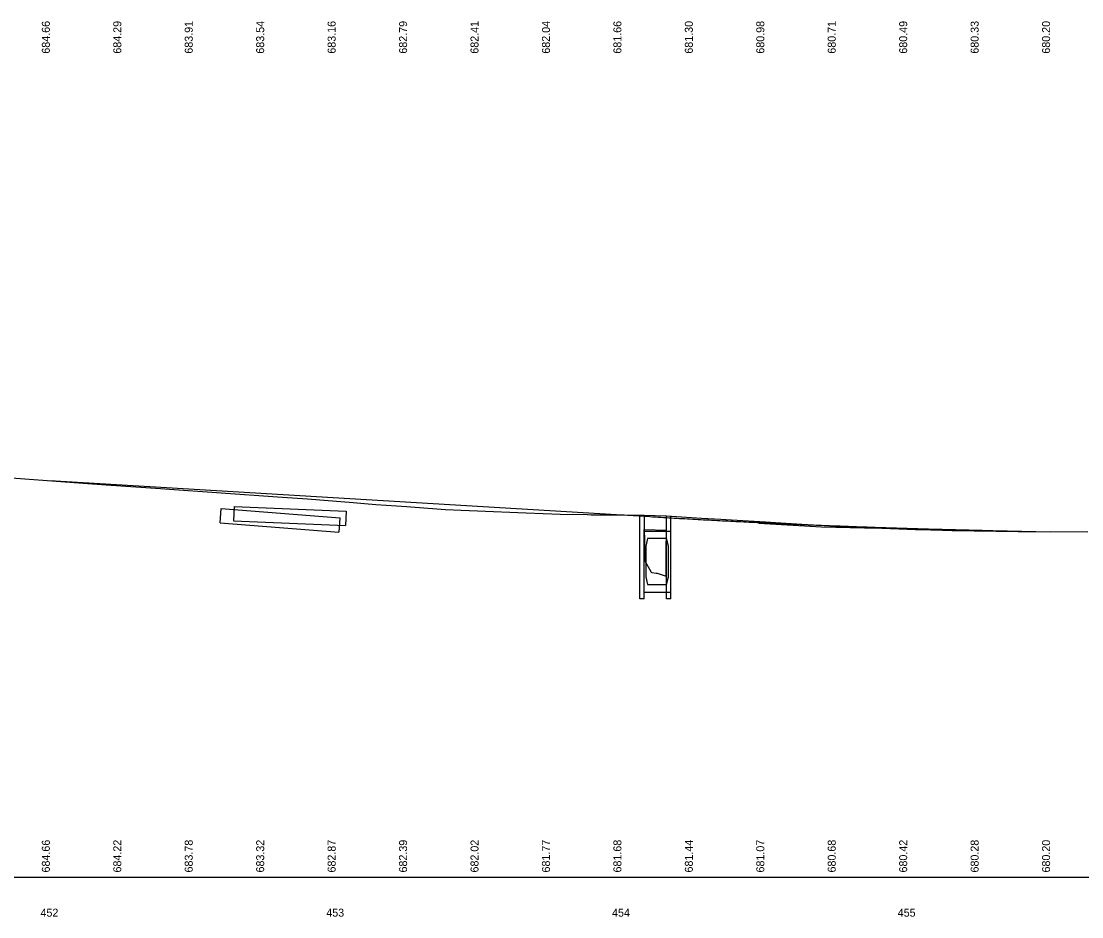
# Model space of a CAD drawing. Extents: x 157201 to 163282, y 424960 to 427200.
# Drawn here: x 161796.3 to 162167.4, y 425949.5 to 426262.7 of the extents above; entities that cross this region are included whole.
import ezdxf

# ---------------------------------------------------------------- set-up
doc = ezdxf.new("R2010")
doc.units = 0
for name, color, linetype in [('DR_X_Elev_Flow', 7, 'Continuous'), ('RD_X_Concrete_Pad', 7, 'Continuous'), ('RD_X_Fence', 7, 'Continuous'), ('RD_X_GR_Rt', 7, 'Continuous'), ('SV_X_Shot_Marker', 7, 'Continuous'), ('UT_X_Sanitary_Cells', 7, 'Continuous'), ('UT_X_Water_Cells', 7, 'Continuous')]:
    doc.layers.add(name, color=color, linetype=linetype)

msp = doc.modelspace()

# ---------------------------------------------------------------- linework, layer by layer
at = {"layer": 'DR_X_Elev_Flow'}
for p, q in [((161865.84, 426087.28), (161866.23, 426092.26)), ((161866.23, 426092.26), (161907.78, 426088.98)), ((161907.78, 426088.98), (161907.39, 426084)), ((162012.79, 426060.67), (162012.79, 426089.98)), ((162014.28, 426089.96), (162022.07, 426089.69)), ((162023.55, 426060.67), (162023.55, 426089.59)), ((161865.84, 426087.28), (161907.39, 426084)), ((162014.29, 426060.67), (162014.29, 426084.96)), ((162014.29, 426084.96), (162022.05, 426084.69)), ((162022.05, 426060.67), (162022.05, 426084.69)), ((162014.29, 426060.67), (162012.79, 426060.67)), ((162023.55, 426060.67), (162022.05, 426060.67))]:
    msp.add_line(p, q, dxfattribs=at)
at = {"layer": 'RD_X_Concrete_Pad'}
for p, q in [((161806.29, 426102.02), (162016.29, 426089.42)), ((162136.29, 426084.57), (162156.29, 426084.15))]:
    msp.add_line(p, q, dxfattribs=at)
msp.add_open_spline([(162016.29, 426089.42), (162076.29, 426085.82), (162136.29, 426084.57)], degree=2, dxfattribs=at)
at = {"layer": 'SV_X_Shot_Marker'}
for p, q in [((162054.42, 426087.13), (162076.29, 426085.82)), ((162076.29, 426085.82), (162096.33, 426085.4)), ((161406.29, 425963.36), (162615.86, 425963.36))]:
    msp.add_line(p, q, dxfattribs=at)
at = {"layer": 'UT_X_Sanitary_Cells'}
for p, q in [((161870.77, 426092.92), (161870.57, 426087.92)), ((161870.77, 426092.92), (161909.96, 426091.32)), ((161909.96, 426091.32), (161909.76, 426086.32)), ((161870.57, 426087.92), (161909.76, 426086.32)), ((162014.12, 426084.39), (162023.46, 426084.39)), ((162014.12, 426084.39), (162014.12, 426063.05)), ((162023.46, 426084.39), (162023.46, 426063.05)), ((162015.46, 426081.72), (162014.79, 426079.05)), ((162022.12, 426081.72), (162015.46, 426081.72)), ((162022.79, 426079.05), (162022.12, 426081.72)), ((162014.79, 426079.05), (162014.79, 426068.39)), ((162022.79, 426068.39), (162022.79, 426079.05)), ((162014.79, 426068.39), (162015.46, 426065.72)), ((162015.46, 426065.72), (162022.12, 426065.72)), ((162022.12, 426065.72), (162022.79, 426068.39)), ((162014.12, 426063.05), (162023.46, 426063.05))]:
    msp.add_line(p, q, dxfattribs=at)
at = {"layer": 'UT_X_Water_Cells'}
msp.add_lwpolyline([(161774.19, 426104.4), (161797.53, 426102.67), (161821.14, 426100.92), (161821.33, 426100.91), (161825.96, 426100.59), (161844.98, 426099.27), (161846.47, 426099.18), (161885.94, 426096.3), (161896.4, 426095.68), (161912.45, 426094.32), (161920.34, 426093.7), (161927.56, 426093.18), (161931.09, 426092.93), (161944.71, 426091.89), (161950.27, 426091.67), (161958.68, 426091.35), (161970.03, 426090.91), (161972.98, 426090.79), (161984.81, 426090.3), (161994.37, 426090.12), (161995.69, 426090.11), (162007.23, 426090.09), (162014.28, 426089.96), (162014.43, 426076.08), (162014.44, 426074.11), (162014.51, 426073.99), (162016.67, 426070.04), (162016.9, 426069.94), (162018.4, 426069.67), (162018.53, 426069.64), (162018.75, 426069.66), (162021.57, 426068.67), (162021.98, 426068.62), (162022, 426072.27), (162022.07, 426089.69), (162034.26, 426088.92), (162041.11, 426088.51), (162042.88, 426088.4), (162056.66, 426087.61), (162063.81, 426087.15), (162069.39, 426086.8), (162081.19, 426086.08), (162086.52, 426085.88), (162090.2, 426085.75), (162094.53, 426085.45), (162109.23, 426084.93), (162114.51, 426084.75), (162118.7, 426084.64), (162122.03, 426084.62), (162145.11, 426084.23), (162169.53, 426084.06)], dxfattribs=at)

# ---------------------------------------------------------------- texts
at = {"layer": 'RD_X_Fence'}
for s, p in [('684.66', (161806.29, 425964.97)), ('684.22', (161831.29, 425964.97)), ('683.78', (161856.29, 425964.97)), ('683.32', (161881.29, 425964.97)), ('682.87', (161906.29, 425964.97)), ('682.39', (161931.29, 425964.97)), ('682.02', (161956.29, 425964.97)), ('681.77', (161981.29, 425964.97)), ('681.68', (162006.29, 425964.97)), ('681.44', (162031.29, 425964.97)), ('681.07', (162056.29, 425964.97)), ('680.68', (162081.29, 425964.97)), ('680.42', (162106.29, 425964.97)), ('680.28', (162131.29, 425964.97)), ('680.20', (162156.29, 425964.97))]:
    msp.add_text(s, height=2.8, rotation=90, dxfattribs=at).set_placement(p)
at = {"layer": 'RD_X_GR_Rt'}
for s, p in [('684.66', (161806.29, 426251.33)), ('684.29', (161831.29, 426251.33)), ('683.91', (161856.29, 426251.33)), ('683.54', (161881.29, 426251.33)), ('683.16', (161906.29, 426251.33)), ('682.79', (161931.29, 426251.33)), ('682.41', (161956.29, 426251.33)), ('682.04', (161981.29, 426251.33)), ('681.66', (162006.29, 426251.33)), ('681.30', (162031.29, 426251.33)), ('680.98', (162056.29, 426251.33)), ('680.71', (162081.29, 426251.33)), ('680.49', (162106.29, 426251.33)), ('680.33', (162131.29, 426251.33)), ('680.20', (162156.29, 426251.33))]:
    msp.add_text(s, height=2.8, rotation=90, dxfattribs=at).set_placement(p)
for s, p in [('452', (161803.01, 425949.52)), ('453', (161903.02, 425949.52)), ('454', (162003.02, 425949.52)), ('455', (162102.99, 425949.52))]:
    msp.add_text(s, height=2.8, dxfattribs=at).set_placement(p)

doc.saveas('drawing.dxf')
